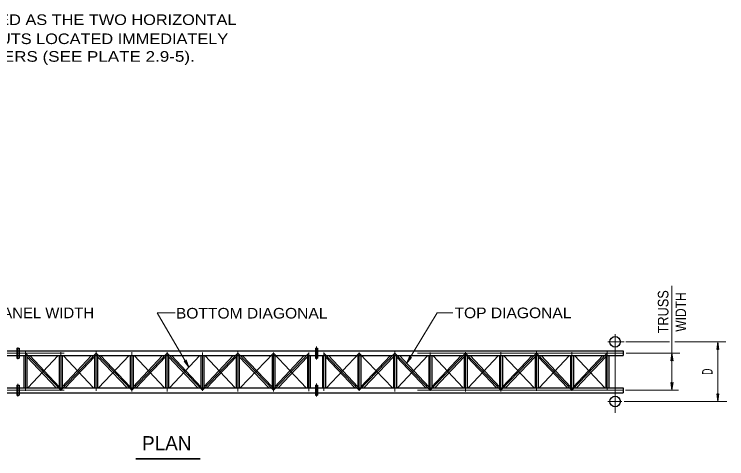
# Model space of a CAD drawing. Extents: x 312601.858 to 312602.699, y 144420.11 to 144420.704.
# Drawn here: x 312602.0675 to 312602.2692, y 144420.3163 to 144420.4421 of the extents above; entities that cross this region are included whole.
import ezdxf
from ezdxf.enums import TextEntityAlignment as Align

# ---------------------------------------------------------------- set-up
doc = ezdxf.new("R2010")
doc.units = 0
doc.header["$LTSCALE"] = 0.0012
doc.linetypes.add('DOT_DASHED', pattern=[7.7, 5, -1.2, 0.3, -1.2])
doc.linetypes.add('LONG_DASHED', pattern=[7.5, 6, -1.5])
for name, color, linetype, lineweight in [('1', 7, 'Continuous', 25), ('2', 7, 'Continuous', 13), ('39', 7, 'Continuous', 13)]:
    doc.layers.add(name, color=color, linetype=linetype, lineweight=lineweight)

msp = doc.modelspace()

# ---------------------------------------------------------------- hatches: boundary and pattern name
at = {"layer": '39'}
for points in [[(312602.2667, 144420.3474), (312602.2664, 144420.3472), (312602.2667, 144420.3494), (312602.267, 144420.3472)], [(312602.2667, 144420.3474), (312602.2664, 144420.3472), (312602.2667, 144420.3494), (312602.267, 144420.3472)], [(312602.1796, 144420.345), (312602.18, 144420.345), (312602.1786, 144420.3433), (312602.1795, 144420.3454)], [(312602.2537, 144420.3442), (312602.2534, 144420.344), (312602.2537, 144420.3462), (312602.254, 144420.344)], [(312602.116, 144420.3439), (312602.1162, 144420.3443), (312602.117, 144420.3422), (312602.1156, 144420.3439)], [(312602.2537, 144420.3377), (312602.254, 144420.3379), (312602.2537, 144420.3357), (312602.2534, 144420.3379)], [(312602.2667, 144420.3345), (312602.267, 144420.3347), (312602.2667, 144420.3325), (312602.2664, 144420.3347)]]:
    msp.add_hatch(color=256, dxfattribs=at).paths.add_polyline_path(points)

# ---------------------------------------------------------------- linework, layer by layer
at = {"layer": '1', "lineweight": 13}
for p, q in [((312602.108, 144420.3576), (312602.117, 144420.3422)), ((312602.108, 144420.3576), (312602.1131, 144420.3576)), ((312602.1786, 144420.3433), (312602.1872, 144420.3576)), ((312602.1872, 144420.3576), (312602.1917, 144420.3576)), ((312602.2406, 144420.3494), (312602.253, 144420.3494)), ((312602.2545, 144420.3494), (312602.2689, 144420.3494)), ((312602.2667, 144420.3494), (312602.2667, 144420.3325)), ((312602.1531, 144420.3481), (312602.1531, 144420.3444)), ((312602.0703, 144420.3455), (312602.0703, 144420.3364)), ((312602.0711, 144420.3455), (312602.0711, 144420.3364)), ((312602.2407, 144420.3462), (312602.2559, 144420.3462)), ((312602.1531, 144420.3376), (312602.1531, 144420.3339)), ((312602.2405, 144420.3357), (312602.2555, 144420.3357)), ((312602.2402, 144420.3325), (312602.2692, 144420.3325))]:
    msp.add_line(p, q, dxfattribs=at)
at = {"layer": '1', "linetype": 'DOT_DASHED', "lineweight": 13}
for p, q in [((312602.2376, 144420.3516), (312602.2376, 144420.3293)), ((312602.2355, 144420.3494), (312602.2402, 144420.3494)), ((312602.0686, 144420.3478), (312602.0686, 144420.3445)), ((312602.0907, 144420.3467), (312602.0907, 144420.3355)), ((312602.1531, 144420.3478), (312602.1531, 144420.3445)), ((312602.2154, 144420.3467), (312602.2154, 144420.3355)), ((312601.9817, 144420.3462), (312602.2401, 144420.3462)), ((312602.0707, 144420.3466), (312602.0707, 144420.3355)), ((312602.0807, 144420.3465), (312602.0807, 144420.3355)), ((312602.1008, 144420.3465), (312602.1008, 144420.3353)), ((312602.1108, 144420.3465), (312602.1108, 144420.3353)), ((312602.1208, 144420.3464), (312602.1208, 144420.3355)), ((312602.1308, 144420.3466), (312602.1308, 144420.3353)), ((312602.1409, 144420.3464), (312602.1409, 144420.3353)), ((312602.1509, 144420.3464), (312602.1509, 144420.3354)), ((312602.1552, 144420.3464), (312602.1552, 144420.3355)), ((312602.1652, 144420.3464), (312602.1652, 144420.3355)), ((312602.1753, 144420.3466), (312602.1753, 144420.3353)), ((312602.1853, 144420.3464), (312602.1853, 144420.3355)), ((312602.1953, 144420.3465), (312602.1953, 144420.3353)), ((312602.2053, 144420.3465), (312602.2053, 144420.3353)), ((312602.2254, 144420.3465), (312602.2254, 144420.3355)), ((312602.2354, 144420.3466), (312602.2354, 144420.3356)), ((312602.0686, 144420.3375), (312602.0686, 144420.3339)), ((312602.1531, 144420.3373), (312602.1531, 144420.3341)), ((312601.9817, 144420.3357), (312602.2401, 144420.3357)), ((312602.2355, 144420.3325), (312602.2395, 144420.3325))]:
    msp.add_line(p, q, dxfattribs=at)
at = {"layer": '1'}
for p, q in [((312601.9817, 144420.3469), (312602.2399, 144420.3469)), ((312602.0683, 144420.3476), (312602.0683, 144420.3448)), ((312602.0683, 144420.3476), (312602.0689, 144420.3476)), ((312602.0689, 144420.3476), (312602.0689, 144420.3448)), ((312602.1528, 144420.3476), (312602.1528, 144420.3448)), ((312602.1528, 144420.3476), (312602.1534, 144420.3476)), ((312602.1534, 144420.3476), (312602.1534, 144420.3448)), ((312602.2399, 144420.3469), (312602.2399, 144420.3455)), ((312601.9817, 144420.3455), (312602.2399, 144420.3455)), ((312602.0683, 144420.3448), (312602.0689, 144420.3448)), ((312602.0703, 144420.3455), (312602.0703, 144420.3364)), ((312602.0711, 144420.3455), (312602.0711, 144420.3364)), ((312602.0794, 144420.3364), (312602.0711, 144420.3452)), ((312602.0803, 144420.3367), (312602.072, 144420.3455)), ((312602.0803, 144420.3455), (312602.0803, 144420.3364)), ((312602.0894, 144420.3455), (312602.0811, 144420.3367)), ((312602.0811, 144420.3455), (312602.0811, 144420.3364)), ((312602.0903, 144420.3452), (312602.082, 144420.3364)), ((312602.0903, 144420.3455), (312602.0903, 144420.3364)), ((312602.0911, 144420.3455), (312602.0911, 144420.3364)), ((312602.0995, 144420.3364), (312602.0911, 144420.3452)), ((312602.1004, 144420.3367), (312602.092, 144420.3455)), ((312602.1004, 144420.3455), (312602.1004, 144420.3364)), ((312602.1095, 144420.3455), (312602.1012, 144420.3367)), ((312602.1012, 144420.3455), (312602.1012, 144420.3364)), ((312602.1104, 144420.3452), (312602.1021, 144420.3364)), ((312602.1104, 144420.3455), (312602.1104, 144420.3364)), ((312602.1112, 144420.3455), (312602.1112, 144420.3364)), ((312602.1195, 144420.3364), (312602.1112, 144420.3452)), ((312602.1204, 144420.3367), (312602.1121, 144420.3455)), ((312602.1204, 144420.3455), (312602.1204, 144420.3364)), ((312602.1295, 144420.3455), (312602.1212, 144420.3367)), ((312602.1212, 144420.3455), (312602.1212, 144420.3364)), ((312602.1304, 144420.3452), (312602.1221, 144420.3364)), ((312602.1304, 144420.3455), (312602.1304, 144420.3364)), ((312602.1312, 144420.3455), (312602.1312, 144420.3364)), ((312602.1396, 144420.3364), (312602.1312, 144420.3452)), ((312602.1405, 144420.3367), (312602.1321, 144420.3455)), ((312602.1405, 144420.3455), (312602.1405, 144420.3364)), ((312602.1496, 144420.3455), (312602.1413, 144420.3367)), ((312602.1413, 144420.3455), (312602.1413, 144420.3364)), ((312602.1505, 144420.3452), (312602.1422, 144420.3364)), ((312602.1505, 144420.3455), (312602.1505, 144420.3364)), ((312602.1513, 144420.3455), (312602.1513, 144420.3364)), ((312602.1528, 144420.3448), (312602.1534, 144420.3448)), ((312602.1548, 144420.3455), (312602.1548, 144420.3364)), ((312602.1556, 144420.3455), (312602.1556, 144420.3364)), ((312602.1556, 144420.3452), (312602.1639, 144420.3364)), ((312602.1565, 144420.3455), (312602.1648, 144420.3367)), ((312602.1648, 144420.3455), (312602.1648, 144420.3364)), ((312602.1656, 144420.3367), (312602.174, 144420.3455)), ((312602.1656, 144420.3455), (312602.1656, 144420.3364)), ((312602.1665, 144420.3364), (312602.1749, 144420.3452)), ((312602.1749, 144420.3455), (312602.1749, 144420.3364)), ((312602.1757, 144420.3455), (312602.1757, 144420.3364)), ((312602.1757, 144420.3452), (312602.184, 144420.3364)), ((312602.1766, 144420.3455), (312602.1849, 144420.3367)), ((312602.1849, 144420.3455), (312602.1849, 144420.3364)), ((312602.1857, 144420.3367), (312602.194, 144420.3455)), ((312602.1857, 144420.3455), (312602.1857, 144420.3364)), ((312602.1866, 144420.3364), (312602.1949, 144420.3452)), ((312602.1949, 144420.3455), (312602.1949, 144420.3364)), ((312602.1957, 144420.3455), (312602.1957, 144420.3364)), ((312602.1957, 144420.3452), (312602.204, 144420.3364)), ((312602.1966, 144420.3455), (312602.2049, 144420.3367)), ((312602.2049, 144420.3455), (312602.2049, 144420.3364)), ((312602.2057, 144420.3367), (312602.2141, 144420.3455)), ((312602.2057, 144420.3455), (312602.2057, 144420.3364)), ((312602.2066, 144420.3364), (312602.215, 144420.3452)), ((312602.215, 144420.3455), (312602.215, 144420.3364)), ((312602.2158, 144420.3455), (312602.2158, 144420.3364)), ((312602.2158, 144420.3452), (312602.2241, 144420.3364)), ((312602.2167, 144420.3455), (312602.225, 144420.3367)), ((312602.225, 144420.3455), (312602.225, 144420.3364)), ((312602.2258, 144420.3367), (312602.2341, 144420.3455)), ((312602.2258, 144420.3455), (312602.2258, 144420.3364)), ((312602.2267, 144420.3364), (312602.235, 144420.3452)), ((312602.235, 144420.3455), (312602.235, 144420.3364)), ((312602.2358, 144420.3455), (312602.2358, 144420.3364)), ((312602.0683, 144420.3371), (312602.0683, 144420.3343)), ((312602.0683, 144420.3371), (312602.0689, 144420.3371)), ((312602.0689, 144420.3371), (312602.0689, 144420.3343)), ((312602.1528, 144420.3371), (312602.1528, 144420.3343)), ((312602.1528, 144420.3371), (312602.1534, 144420.3371)), ((312602.1534, 144420.3371), (312602.1534, 144420.3343)), ((312601.9817, 144420.3364), (312602.2399, 144420.3364)), ((312601.9817, 144420.335), (312602.2399, 144420.335)), ((312602.2399, 144420.3364), (312602.2399, 144420.335)), ((312602.0683, 144420.3343), (312602.0689, 144420.3343)), ((312602.1528, 144420.3343), (312602.1534, 144420.3343))]:
    msp.add_line(p, q, dxfattribs=at)
at = {"layer": '1', "linetype": 'LONG_DASHED', "lineweight": 13}
for p, q in [((312602.08, 144420.3455), (312602.0714, 144420.3364)), ((312602.09, 144420.3364), (312602.0814, 144420.3455)), ((312602.1001, 144420.3455), (312602.0914, 144420.3364)), ((312602.1101, 144420.3364), (312602.1015, 144420.3455)), ((312602.1201, 144420.3455), (312602.1115, 144420.3364)), ((312602.1301, 144420.3364), (312602.1215, 144420.3455)), ((312602.1409, 144420.3462), (312602.1315, 144420.3364)), ((312602.1502, 144420.3364), (312602.1409, 144420.3462)), ((312602.1559, 144420.3364), (312602.1652, 144420.3462)), ((312602.1652, 144420.3462), (312602.1746, 144420.3364)), ((312602.176, 144420.3364), (312602.1846, 144420.3455)), ((312602.186, 144420.3455), (312602.1946, 144420.3364)), ((312602.196, 144420.3364), (312602.2046, 144420.3455)), ((312602.206, 144420.3455), (312602.2147, 144420.3364)), ((312602.2161, 144420.3364), (312602.2247, 144420.3455)), ((312602.2261, 144420.3455), (312602.2347, 144420.3364))]:
    msp.add_line(p, q, dxfattribs=at)
at = {"layer": '1', "lineweight": 13}
msp.add_lwpolyline([(312602.2537, 144420.3653), (312602.2537, 144420.3462), (312602.2537, 144420.3357)], dxfattribs=at)
at = {"layer": '1', "linetype": 'DOT_DASHED', "lineweight": 13}
for points in [[(312602.1509, 144420.3462), (312602.1409, 144420.3357), (312602.1308, 144420.3462), (312602.1208, 144420.3357), (312602.1108, 144420.3462), (312602.1008, 144420.3357), (312602.0907, 144420.3462), (312602.0807, 144420.3357), (312602.0707, 144420.3462)], [(312602.1552, 144420.3462), (312602.1652, 144420.3357), (312602.1753, 144420.3462), (312602.1853, 144420.3357), (312602.1953, 144420.3462), (312602.2053, 144420.3357), (312602.2154, 144420.3462), (312602.2254, 144420.3357), (312602.2354, 144420.3462)]]:
    msp.add_lwpolyline(points, dxfattribs=at)
at = {"layer": '1'}
for centre in [(312602.2376, 144420.3494), (312602.2376, 144420.3325)]:
    msp.add_circle(centre, 0.0015, dxfattribs=at)
at = {"layer": '2', "lineweight": 35}
msp.add_line((312602.102, 144420.3163), (312602.1202, 144420.3163), dxfattribs=at)
at = {"layer": '39'}
for points in [[(312602.2667, 144420.3474), (312602.2664, 144420.3472), (312602.2667, 144420.3494), (312602.267, 144420.3472)], [(312602.2667, 144420.3474), (312602.2664, 144420.3472), (312602.2667, 144420.3494), (312602.267, 144420.3472)], [(312602.1796, 144420.345), (312602.18, 144420.345), (312602.1786, 144420.3433), (312602.1795, 144420.3454)], [(312602.2537, 144420.3442), (312602.2534, 144420.344), (312602.2537, 144420.3462), (312602.254, 144420.344)], [(312602.116, 144420.3439), (312602.1162, 144420.3443), (312602.117, 144420.3422), (312602.1156, 144420.3439)], [(312602.2537, 144420.3377), (312602.254, 144420.3379), (312602.2537, 144420.3357), (312602.2534, 144420.3379)], [(312602.2667, 144420.3345), (312602.267, 144420.3347), (312602.2667, 144420.3325), (312602.2664, 144420.3347)]]:
    msp.add_lwpolyline(points, close=True, dxfattribs=at)

# ---------------------------------------------------------------- texts
at = {"layer": '2'}
for s, width, p in [('END STRUTS ARE DEFINED AS THE TWO HORIZONTAL', 1.15, (312602.06905, 144420.4391)), ('AND TWO VERTICAL STRUTS LOCATED IMMEDIATELY', 1.15, (312602.0676, 144420.4337)), ('ADJACENT TO THE TOWERS (SEE PLATE 2.9-5).', 1.2, (312602.063, 144420.4287)), ('PANEL WIDTH', 1.05, (312602.07575, 144420.3561)), ('BOTTOM DIAGONAL', 1.1, (312602.13475, 144420.356)), ('TOP DIAGONAL', 1.1, (312602.2087, 144420.3561))]:
    msp.add_text(s, height=0.003, dxfattribs=dict(at, width=width)).set_placement(p, align=Align.CENTER)
for s, width, p in [('TRUSS', 0.9, (312602.2527, 144420.3579)), ('WIDTH', 0.85, (312602.2577, 144420.35785)), ('D', 0.6, (312602.2652, 144420.34095))]:
    msp.add_text(s, height=0.003, rotation=90, dxfattribs=dict(at, width=width)).set_placement(p, align=Align.CENTER)
msp.add_text('PLAN', height=0.004, dxfattribs=at).set_placement((312602.1107, 144420.3187), align=Align.CENTER)

doc.saveas('drawing.dxf')
